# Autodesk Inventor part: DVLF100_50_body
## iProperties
Created: 2010-03
Part Number: DVLF100_50_body
Document SubType Name: Modeling
Designer: TB
Mass: 2348.37 g
Surface Area: 2593.57 cm^2
Volume: 2348.37 cm^3
Density: 1 g/cm^3
Author: TB
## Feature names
1. Kropp [Revolution]
2. Chamfer
3. Extrusion2
4. Hole1
5. Revolution2
6. Hole2
7. Fillet1
8. Extrusion3
9. Hole3
